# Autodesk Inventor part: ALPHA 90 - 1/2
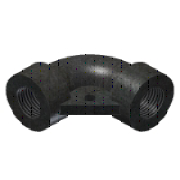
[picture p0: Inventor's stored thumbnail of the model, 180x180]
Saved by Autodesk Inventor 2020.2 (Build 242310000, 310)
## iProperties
Manager: www.cadconsulting.pl
Company: Fabian Stasiak CAD Consulting
Created: 2014-09
Part Number: ALPHA 90 - 1/2
Material: Stal
Description: Kolanko stalowe gwint. kąt 90, ALPHA
Document SubType Name: Modeling
Standard: ALPHA-010102
Designer: F.Stasiak
Manufacturer: ALPHA
Standards Organization: ANSI
Language: pl-PL
Size Designation: 1/2
Categories: <MemberInstance><Categories><Category DisplayName="Rury cienko- i grubościenne" InternalName="4347fa0f-2144-441d-94cd-e3e15c92b736" Mnemonic="TUBEANDPIPE"><Cate
Density: 7.85 g/cm^3
Appearance: Płyta
Catalog Web Link: www.expertbooks.pl
IsCustomPart: 0
Author: F.Stasiak
Subject: Zbiór ćwiczeń. Autodesk Inventor 2020. Kurs Professional
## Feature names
1. Przeciągnięcie1
2. Wyciągnięcie proste1 [Extrusion]
3. Wyciągnięcie proste2 [Extrusion]
4. Wyciągnięcie proste5 [Extrusion]
## Parameters: d0 = 45.7835 mm, d1 = 45.7835 mm, d2 = 22.89175 mm, d4 = 0, d5 = 0, d6 = 33.02 mm, d7 = 18.3134 mm, d9 = 15.748 mm, d10 = 0, d11 = 33.02 mm, d12 = 15.748 mm, d13 = 0, d19 = 19.8628 mm, d20 = 0, d21 = 19.8628 mm, d22 = 0, ID = 18.3134 mm, OD = 33.02 mm, GL = 15.748 mm, G = 3.175 mm, d23 = 3.175 mm, d24 = 6.35 mm, d26 = 6.35 mm, d27 = 0
